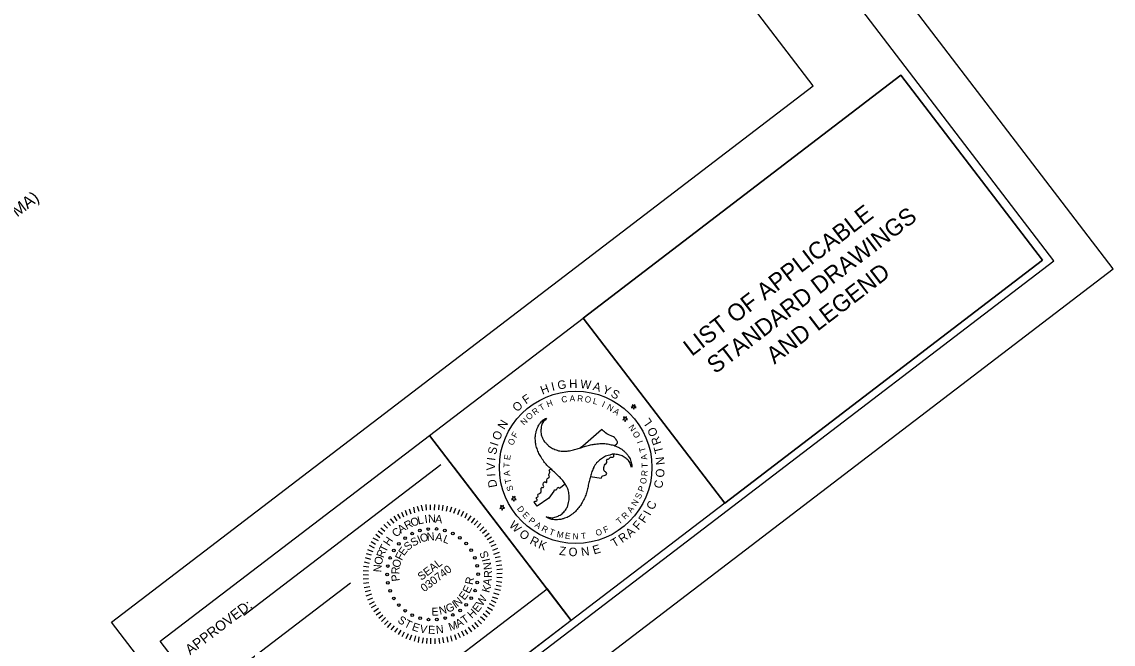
# Model space of a CAD drawing. Extents: x -642 to 2005, y -4412 to 1950.
# Drawn here: x 1361 to 2005, y 854 to 1222 of the extents above; entities that cross this region are included whole.
import ezdxf

# ---------------------------------------------------------------- set-up
doc = ezdxf.new("R2010")
doc.units = 0
for name, color, linetype in [('DEV BORDER CELL', 7, 'Continuous'), ('DEV DOT SWIRL SEAL CELL', 7, 'Continuous'), ('Old_Level_9', 7, 'Continuous'), ('Scratch_Level_0', 7, 'Continuous'), ('Scratch_Level_6', 7, 'Continuous'), ('Sheet Plot Border Outside CELL', 7, 'Continuous'), ('Sheet Sticker Exception Certification CELL', 7, 'Continuous'), ('Text', 7, 'Continuous')]:
    doc.layers.add(name, color=color, linetype=linetype)

msp = doc.modelspace()

# ---------------------------------------------------------------- linework, layer by layer
at = {"layer": 'DEV BORDER CELL'}
for p, q in [((1491.66, 871.26), (1607.91, 960.15)), ((1615.53, 958.66), (1684.78, 868.1)), ((1491.28, 841.93), (1554.67, 890.39))]:
    msp.add_line(p, q, dxfattribs=at)
for points in [[(1331.69, 1914.53), (140.13, 1003.39), (777.93, 169.29), (1969.49, 1080.44)], [(1879.29, 1189.93), (1691.82, 1046.58), (1775.34, 937.35), (1962.81, 1080.7)], [(1601.26, 977.33), (1691.82, 1046.58), (1775.34, 937.35), (1684.78, 868.1)], [(1442.35, 855.82), (1601.26, 977.33), (1684.78, 868.1), (1525.88, 746.59)]]:
    msp.add_lwpolyline(points, close=True, dxfattribs=at)
at = {"layer": 'DEV DOT SWIRL SEAL CELL'}
for p, q in [((1721.05, 994.41), (1720.19, 993.75)), ((1720.19, 993.75), (1721.28, 993.78)), ((1721.59, 994.82), (1720.7, 995.4)), ((1720.7, 995.4), (1721.05, 994.41)), ((1721.28, 993.78), (1721.66, 992.75)), ((1722.45, 995.48), (1721.59, 994.82)), ((1721.66, 992.75), (1721.94, 993.78)), ((1721.94, 993.78), (1723.03, 993.8)), ((1722.14, 994.44), (1722.45, 995.48)), ((1723.03, 993.8), (1722.14, 994.44)), ((1716.08, 987.28), (1715.22, 986.62)), ((1715.22, 986.62), (1716.31, 986.65)), ((1716.62, 987.7), (1715.73, 988.27)), ((1715.73, 988.27), (1716.08, 987.28)), ((1716.31, 986.65), (1716.69, 985.63)), ((1717.48, 988.36), (1716.62, 987.7)), ((1716.69, 985.63), (1716.97, 986.65)), ((1716.97, 986.65), (1718.06, 986.68)), ((1717.17, 987.31), (1717.48, 988.36)), ((1718.06, 986.68), (1717.17, 987.31)), ((1696.17, 953.14), (1702.42, 952.05)), ((1677.86, 946.22), (1681.23, 948.75)), ((1650.41, 940.2), (1649.55, 939.54)), ((1650.95, 940.61), (1650.06, 941.19)), ((1650.06, 941.19), (1650.41, 940.2)), ((1651.81, 941.27), (1650.95, 940.61)), ((1651.5, 940.22), (1651.81, 941.27)), ((1652.39, 939.59), (1651.5, 940.22)), ((1671.62, 940.37), (1664.76, 935.53)), ((1674.58, 944.42), (1671.62, 940.37)), ((1643.51, 934.94), (1642.65, 934.28)), ((1642.65, 934.28), (1643.74, 934.3)), ((1644.05, 935.35), (1643.15, 935.93)), ((1643.15, 935.93), (1643.51, 934.94)), ((1643.74, 934.3), (1644.12, 933.28)), ((1644.91, 936.01), (1644.05, 935.35)), ((1644.12, 933.28), (1644.4, 934.3)), ((1644.4, 934.3), (1645.49, 934.33)), ((1644.4, 934.3), (1645.49, 934.33)), ((1644.6, 934.96), (1644.91, 936.01)), ((1644.6, 934.96), (1644.91, 936.01)), ((1645.49, 934.33), (1644.6, 934.96)), ((1645.49, 934.33), (1644.6, 934.96)), ((1649.55, 939.54), (1650.64, 939.57)), ((1650.64, 939.57), (1651.02, 938.54)), ((1651.02, 938.54), (1651.3, 939.56)), ((1651.3, 939.56), (1652.39, 939.59)), ((1664.76, 935.53), (1663.22, 937.69))]:
    msp.add_line(p, q, dxfattribs=at)
for start, end in [(308.60748, 312.72752), (303.08246, 303.3802)]:
    msp.add_arc((1544.46, 1152.18), 233.19, start, end, dxfattribs=at)
for points in [[(1670.02, 929.33), (1672.63, 928.79), (1675.2, 929), (1677.58, 930.01), (1679.91, 931.59), (1681.79, 933.87), (1682.72, 935.8), (1682.96, 936.8), (1683.4, 938.52), (1683.54, 939.97), (1683.43, 942.86), (1682.76, 945.86), (1681.24, 948.73), (1681.1, 948.96), (1679.25, 951.33), (1677.09, 953.49), (1674.97, 955.56), (1672.7, 957.64), (1670.49, 959.74), (1668.67, 962.03), (1666.78, 964.81), (1665.42, 967.38), (1664.38, 970.3), (1663.93, 971.72), (1663.8, 973.04), (1663.57, 976.21), (1664.08, 979.3), (1664.59, 981.11), (1665.26, 982.57), (1665.38, 982.82), (1667.08, 985.28), (1669.23, 987.06), (1670.13, 987.44)], [(1670.14, 987.55), (1670.13, 987.44), (1668.37, 985.49), (1667.25, 983.11), (1666.93, 980.57), (1667.14, 977.78), (1668.18, 975), (1669.36, 973.23), (1670.13, 972.54), (1671.4, 971.28), (1672.57, 970.41), (1675.15, 969.11), (1678.07, 968.17), (1681.33, 968.06), (1681.6, 968.06), (1684.54, 968.45), (1687.54, 969.26), (1690.37, 970.07), (1693.29, 970.98), (1696.23, 971.81), (1699.13, 972.27), (1702.48, 972.53), (1705.37, 972.41), (1708.42, 971.88), (1709.89, 971.54), (1711.09, 970.98), (1713.96, 969.62), (1716.37, 967.62), (1717.7, 966.27), (1718.64, 964.96), (1718.81, 964.75), (1720.05, 962.01), (1720.5, 959.25), (1720.4, 958.33)], [(1710.35, 971.35), (1712.13, 973.09), (1711.23, 974.87), (1710.26, 976.18), (1708.3, 977.07), (1704.98, 978.9), (1702.68, 980.88)], [(1720.4, 958.33), (1719.58, 960.81), (1718.11, 962.96), (1716.04, 964.52), (1713.52, 965.74), (1710.61, 966.22), (1708.49, 966.08), (1707.49, 965.76), (1705.78, 965.33), (1704.42, 964.69), (1702.01, 963.15), (1699.72, 961.07), (1698.01, 958.31), (1697.88, 958.07), (1696.77, 955.3), (1695.95, 952.34), (1695.2, 949.47), (1694.56, 946.47), (1693.83, 943.49), (1692.76, 940.77), (1691.3, 937.73), (1689.75, 935.3), (1687.77, 932.94), (1686.74, 931.81), (1685.66, 931.06), (1683.07, 929.28), (1680.11, 928.16), (1678.3, 927.69), (1676.68, 927.56), (1676.4, 927.52), (1673.43, 927.79), (1670.83, 928.77), (1670.02, 929.33)], [(1702.42, 952.05), (1703.46, 953.48), (1704.91, 953.92), (1705.52, 954.24), (1705.71, 954.92), (1704.29, 956.5), (1704.07, 957.58), (1704.86, 960.31), (1705.79, 961.42), (1705.83, 963.09), (1706.19, 963.32), (1706.92, 963.42), (1707.9, 964.53), (1709.38, 964.49), (1709.89, 964.94), (1709.67, 966.12)], [(1663.22, 937.69), (1663, 937.84), (1663.19, 938.34), (1664.48, 938.69), (1664.65, 939.49), (1664.3, 939.9), (1664.38, 940.64), (1665.15, 941.02), (1665.18, 942.24), (1665.62, 942.83), (1666.81, 943.74), (1667.14, 946.23), (1667.65, 946.77), (1668.1, 946.51), (1668.51, 946.72), (1668.25, 948.36), (1668.29, 948.64), (1669.02, 949.91), (1669.48, 949.91), (1669.97, 949.47), (1670.19, 949.5), (1670.36, 950.02), (1670.38, 951.02), (1670.91, 952.18), (1672.05, 952.84), (1671.58, 953.83), (1672.17, 955.56), (1672.04, 956.24), (1671.73, 956.79)], [(1677.86, 946.22), (1677.2, 946.53), (1676.54, 946.27), (1676.09, 945.32), (1675.53, 944.93), (1674.58, 944.92), (1674.58, 944.42)]]:
    msp.add_spline(points, degree=3, dxfattribs=at)
at = {"layer": 'Old_Level_9'}
for p, q in [((1589.12, 934.01), (1590.24, 931.1)), ((1591.66, 935.01), (1592.29, 931.72)), ((1593.95, 935.51), (1594.81, 932.54)), ((1596.35, 936.08), (1596.98, 932.79)), ((1598.99, 936.53), (1599.18, 933.21)), ((1601.57, 936.46), (1601.6, 933.33)), ((1604.07, 936.48), (1604, 933.28)), ((1606.65, 936.4), (1606.42, 933.4)), ((1609.02, 936.17), (1608.68, 932.92)), ((1611.63, 935.65), (1610.96, 932.62)), ((1614.13, 935.05), (1613.11, 932.06)), ((1616.44, 934.29), (1615.42, 931.31)), ((1578.07, 928.09), (1580.05, 925.5)), ((1580.16, 929.68), (1581.83, 926.87)), ((1582.27, 930.83), (1583.9, 928.29)), ((1584.59, 932.12), (1585.91, 929.36)), ((1586.78, 933.17), (1587.9, 930.25)), ((1618.82, 933.44), (1617.63, 930.48)), ((1621.18, 932.41), (1619.64, 929.5)), ((1623.27, 931.33), (1622, 928.47)), ((1625.66, 929.85), (1623.68, 927.09)), ((1627.7, 928.42), (1625.75, 925.83)), ((1570.89, 921.02), (1573.48, 919.07)), ((1572.47, 922.86), (1574.79, 920.85)), ((1574.33, 924.75), (1576.35, 922.52)), ((1576.14, 926.29), (1578.26, 924.14)), ((1629.64, 926.92), (1627.53, 924.52)), ((1631.38, 925.26), (1629.37, 922.94)), ((1633.17, 923.32), (1630.82, 921.05)), ((1634.86, 921.31), (1632.38, 919.42)), ((1566.75, 914.7), (1569.39, 913.1)), ((1567.83, 916.79), (1570.84, 915.32)), ((1569.46, 918.98), (1571.97, 917.13)), ((1636.31, 919.43), (1633.82, 917.53)), ((1637.8, 917.27), (1635.27, 915.64)), ((1639.2, 915.03), (1636.43, 913.7)), ((1564.59, 909.91), (1567.75, 908.86)), ((1565.57, 912.54), (1568.58, 911.07)), ((1640.34, 912.92), (1637.33, 911.71)), ((1641.29, 910.65), (1638.27, 909.45)), ((1642.21, 908.21), (1638.95, 907.13)), ((1562.56, 902.69), (1565.59, 902.02)), ((1563.16, 905.2), (1566.34, 904.33)), ((1563.84, 907.6), (1566.85, 906.76)), ((1642.93, 905.61), (1639.84, 905.14)), ((1643.43, 903.32), (1640.41, 902.74)), ((1561.98, 897.68), (1565.16, 897.44)), ((1562.1, 895.26), (1565.2, 895.11)), ((1562.31, 900.14), (1565.39, 899.82)), ((1643.88, 900.67), (1640.63, 900.39)), ((1644.2, 898.4), (1640.86, 898.04)), ((1644.13, 895.83), (1640.98, 895.62)), ((1562.1, 892.59), (1565.27, 892.97)), ((1562.23, 890.16), (1565.4, 890.54)), ((1643.47, 888.24), (1640.52, 888.82)), ((1643.87, 890.6), (1640.64, 891.12)), ((1644.05, 893.25), (1640.95, 893.4)), ((1562.67, 887.52), (1565.97, 888.15)), ((1563.25, 885.12), (1566.39, 885.95)), ((1563.9, 882.63), (1567.08, 883.81)), ((1642.19, 883.33), (1639.18, 884.18)), ((1643.05, 885.71), (1639.76, 886.51)), ((1564.74, 880.28), (1567.76, 881.49)), ((1565.84, 877.82), (1568.7, 879.22)), ((1566.99, 875.71), (1569.7, 877.31)), ((1638.28, 874.04), (1635.39, 875.77)), ((1639.56, 876.28), (1636.64, 877.83)), ((1640.56, 878.47), (1637.72, 879.91)), ((1641.59, 880.83), (1638.43, 881.87)), ((1568.38, 873.47), (1571.04, 875.34)), ((1569.72, 871.51), (1572.36, 873.21)), ((1571.32, 869.42), (1573.65, 871.52)), ((1572.94, 867.51), (1575.29, 869.78)), ((1633.73, 868.05), (1631.34, 870.15)), ((1635.24, 869.99), (1632.82, 871.92)), ((1636.82, 871.83), (1634.41, 873.76)), ((1574.65, 865.68), (1576.83, 867.97)), ((1576.47, 863.92), (1578.5, 866.41)), ((1578.51, 862.49), (1580.44, 864.91)), ((1580.65, 861.13), (1582.5, 863.65)), ((1626.07, 861.41), (1624.2, 864.06)), ((1628.23, 862.9), (1626.33, 865.38)), ((1630.04, 864.44), (1627.87, 866.87)), ((1631.88, 866.16), (1629.76, 868.32)), ((1582.96, 859.75), (1584.38, 862.42)), ((1585.04, 858.67), (1586.39, 861.44)), ((1587.38, 857.47), (1588.75, 860.41)), ((1589.59, 856.64), (1590.79, 859.6)), ((1592.25, 855.84), (1593.02, 858.95)), ((1594.65, 855.16), (1595.17, 858.39)), ((1597.01, 854.76), (1597.6, 857.89)), ((1599.66, 854.58), (1599.8, 857.69)), ((1602.04, 854.36), (1602.03, 857.66)), ((1604.61, 854.28), (1604.51, 857.5)), ((1607.23, 854.55), (1606.85, 857.73)), ((1609.68, 854.85), (1609.13, 858.05)), ((1612.15, 855.33), (1611.57, 858.35)), ((1614.65, 855.97), (1613.82, 859.12)), ((1617.06, 856.72), (1616.04, 859.71)), ((1619.45, 857.92), (1618.13, 860.68)), ((1621.72, 858.86), (1620.32, 861.73)), ((1623.83, 860.01), (1622.31, 862.62))]:
    msp.add_line(p, q, dxfattribs=at)
for centre in [(1595.56, 921.17), (1600.43, 922.09), (1605.39, 922.1), (1610.26, 921.2), (1586.73, 916.75), (1590.94, 919.37), (1614.89, 919.42), (1619.11, 916.82), (1580.1, 909.44), (1583.08, 913.4), (1622.78, 913.49), (1625.77, 909.54), (1577.9, 905), (1627.99, 905.11), (1576.11, 895.29), (1576.55, 900.23), (1629.36, 900.34), (1629.83, 895.41), (1576.57, 890.36), (1629.38, 890.47), (1577.94, 885.59), (1628.03, 885.7), (1580.16, 881.16), (1583.15, 877.21), (1622.85, 877.3), (1625.83, 881.26), (1586.83, 873.88), (1591.04, 871.28), (1595.67, 869.5), (1600.54, 868.6), (1605.5, 868.61), (1610.37, 869.53), (1614.99, 871.33), (1619.2, 873.95)]:
    msp.add_circle(centre, 0.788, dxfattribs=at)
at = {"layer": 'Scratch_Level_0'}
msp.add_lwpolyline([(1322.34, 1844.44), (210.22, 994.04), (787.28, 239.38), (1485.42, 773.22), (1413.58, 867.17), (1827.56, 1183.74)], close=True, dxfattribs=at)
at = {"layer": 'Scratch_Level_6'}
msp.add_lwpolyline([(1691.82, 1046.58), (1879.29, 1189.93), (1962.81, 1080.7), (1775.34, 937.35)], close=True, dxfattribs=at)
at = {"layer": 'Sheet Plot Border Outside CELL'}
msp.add_lwpolyline([(663.64, 50.42), (2004.54, 1075.77), (1336.37, 1949.58), (-4.54, 924.23)], close=True, dxfattribs=at)
at = {"layer": 'Sheet Sticker Exception Certification CELL'}
for p, q in [((1511.6, 765.26), (1670.51, 886.77)), ((1670.51, 886.76), (1684.79, 868.09)), ((1684.78, 868.1), (1525.88, 746.59))]:
    msp.add_line(p, q, dxfattribs=at)
at = {"layer": 'Text'}
msp.add_circle((1687.42, 958.49), 44.97, dxfattribs=at)

# ---------------------------------------------------------------- texts
at = {"layer": 'DEV BORDER CELL'}
for s, height, rotation, p in [('TRUCK MOUNTED ATTENUATOR (TMA)', 7, 37.40424, (1231.07, 1009.02)), ('LIST OF APPLICABLE', 10, 37.40396, (1755.89, 1023.71)), ('STANDARD DRAWINGS ', 10, 37.40396, (1769.71, 1013.29)), ('AND LEGEND', 10, 37.40396, (1804.71, 1019.08)), ('APPROVED:  ', 6, 37.40396, (1459.96, 847.56))]:
    msp.add_text(s, height=height, rotation=rotation, dxfattribs=at).set_placement(p)
at = {"layer": 'DEV DOT SWIRL SEAL CELL'}
for s, height, rotation, p in [('H', 5.04, 20.85795, (1667.77, 1001.37)), ('I', 5.04, 13.208, (1673.67, 1003.53)), ('G', 5.04, 8.92066, (1677.08, 1004.39)), ('H', 5.04, 0.8672, (1683.63, 1005.3)), ('W', 5.04, 353.21724, (1689.9, 1005.32)), ('A', 5.04, 344.18021, (1697.24, 1004.26)), ('Y', 5.04, 337.15234, (1702.77, 1002.64)), ('F', 5.04, 34.66149, (1658.07, 995.58)), ('H', 3.63, 21.03619, (1671.02, 993.89)), ('C', 3.63, 10.88002, (1679.33, 996.57)), ('A', 3.63, 0.72385, (1683.88, 997.37)), ('R', 3.63, 355.64577, (1688.21, 997.47)), ('O', 3.63, 350.56768, (1692.52, 997.1)), ('L', 3.63, 345.4896, (1697.31, 996.13)), ('S', 5.04, 330.62886, (1707.7, 1000.55)), ('O', 5.04, 43.16891, (1652.88, 990.91)), ('R', 3.63, 36.27045, (1663.29, 989.06)), ('I', 3.63, 335.33343, (1702.47, 994.41)), ('N', 3.63, 330.25535, (1705.44, 993.02)), ('A', 3.63, 325.17726, (1709.17, 990.77)), ('N', 5.04, 58.99002, (1645.29, 980.41)), ('N', 3.63, 46.42661, (1657.04, 983.03)), ('O', 3.63, 41.34853, (1659.9, 986.12)), ('O', 5.04, 67.49744, (1642.49, 974.02)), ('F', 3.63, 61.66087, (1652.4, 975.56)), ('N', 3.63, 125.13693, (1723.35, 981.37)), ('O', 3.63, 120.33085, (1725.81, 977.12)), ('I', 5.04, 71.78478, (1641.44, 970.66)), ('O', 3.63, 66.73895, (1650.49, 971.14)), ('I', 3.63, 110.17468, (1727.23, 973.48)), ('S', 5.04, 77.98881, (1640.38, 965.68)), ('E', 3.63, 81.97321, (1648.69, 962.61)), ('T', 3.63, 105.0966, (1728.92, 967.98)), ('A', 3.63, 100.01851, (1729.79, 963.18)), ('V', 5.04, 88.98456, (1639.84, 956.69)), ('I', 5.04, 82.27614, (1639.96, 962.19)), ('T', 3.63, 87.05129, (1648.43, 958.24)), ('T', 3.63, 89.86234, (1729.96, 958.1)), ('I', 5.04, 93.2719, (1640.1, 953.18)), ('A', 3.63, 97.20746, (1648.82, 953.52)), ('R', 3.63, 84.78426, (1729.65, 953.15)), ('D', 5.04, 100.86301, (1641.19, 947.04)), ('T', 3.63, 102.28555, (1649.58, 949.33)), ('S', 3.63, 107.36363, (1650.83, 945.07)), ('P', 3.63, 69.55, (1727.3, 943.69)), ('O', 3.63, 79.70617, (1728.83, 948.41)), ('S', 3.63, 64.47192, (1725.43, 939.36)), ('D', 3.63, 307.67597, (1652.58, 934)), ('A', 3.63, 54.31575, (1720.27, 931.3)), ('N', 3.63, 59.39383, (1723.06, 935.18)), ('E', 3.63, 312.75406, (1655.62, 930.21)), ('P', 3.63, 322.91023, (1659.26, 926.44)), ('T', 3.63, 39.0815, (1713.14, 924.58)), ('R', 3.63, 44.15958, (1716.56, 927.49)), ('A', 3.63, 327.98831, (1662.93, 923.63)), ('R', 3.63, 333.0664, (1666.89, 921.2)), ('T', 3.63, 338.14448, (1671.38, 919.09)), ('M', 3.63, 348.30065, (1675.94, 917.42)), ('O', 3.63, 18.76916, (1699.85, 917.79)), ('F', 3.63, 23.84724, (1704.66, 919.6)), ('E', 3.63, 353.37873, (1680.91, 916.42)), ('N', 3.63, 358.45682, (1685.55, 915.98)), ('T', 3.63, 8.61299, (1690.89, 915.99))]:
    msp.add_text(s, height=height, rotation=rotation, dxfattribs=at).set_placement(p)
at = {"layer": 'Old_Level_9'}
for s, height, rotation, p in [('R', 4.72, 27.42552, (1587.73, 921.63)), ('O', 4.72, 20.49076, (1590.99, 923.33)), ('L', 4.72, 13.14987, (1594.65, 924.72)), ('I', 4.72, 8.20992, (1598.6, 925.53)), ('N', 4.72, 2.3078, (1600.42, 925.82)), ('A', 4.72, 354.40904, (1604.34, 925.83)), ('C', 4.72, 42.34388, (1581.58, 916.92)), ('A', 4.72, 35.37883, (1584.3, 919.32)), ('H', 4.72, 55.14731, (1577.4, 911.68)), ('S', 4.7, 41.87199, (1588.55, 909.03)), ('S', 4.7, 30.44542, (1591.65, 911.56)), ('I', 4.7, 22.88603, (1595.13, 913.59)), ('O', 4.7, 15.27885, (1596.28, 914.15)), ('N', 4.7, 4.79698, (1599.79, 915.11)), ('A', 4.7, 351.34774, (1604.37, 915.31)), ('L', 4.7, 338.93627, (1608.8, 914.45)), ('R', 4.72, 69.57941, (1574.07, 904.72)), ('T', 4.72, 62.83975, (1575.39, 907.93)), ('F', 4.7, 63.80392, (1584.83, 903.2)), ('E', 4.7, 53.9929, (1586.18, 905.96)), ('S', 4.72, 109.66185, (1636.41, 905.67)), ('O', 4.72, 77.34818, (1572.98, 900.59)), ('O', 4.7, 75.65578, (1583.54, 898.91)), ('SEAL', 4.699, 37.40396, (1596.4, 891.48)), ('I', 4.72, 103.45036, (1636.99, 903.46)), ('N', 4.72, 96.77653, (1637.96, 898.23)), ('N', 4.72, 85.47062, (1572.69, 896.43)), ('R', 4.7, 87.15176, (1583.33, 895.28)), ('030740', 4.699, 37.40396, (1598.13, 884.69)), ('R', 4.72, 88.55428, (1637.98, 893.14)), ('P', 4.7, 97.52761, (1583.71, 891.49)), ('E', 4.7, 64.56078, (1624.66, 883.62)), ('R', 4.7, 77.75323, (1626.61, 888.89)), ('K', 4.72, 73.54497, (1636.38, 884.14)), ('A', 4.72, 80.92565, (1637.27, 888.39)), ('E', 4.7, 53.20965, (1621.83, 879.72)), ('W', 4.72, 59.40972, (1632.37, 876.11)), ('E', 4.7, 2.27315, (1602.46, 870.89)), ('N', 4.7, 13.46232, (1607.35, 871.48)), ('G', 4.7, 24.88521, (1612.04, 872.55)), ('I', 4.7, 33.02855, (1616.54, 874.89)), ('N', 4.7, 40.53176, (1617.74, 875.8)), ('E', 4.72, 51.56872, (1629.67, 872.53)), ('S', 4.72, 325.61597, (1581.95, 867.35)), ('T', 4.72, 34.79055, (1621.79, 865.77)), ('H', 4.72, 43.41518, (1626.2, 868.96)), ('T', 4.72, 333.02835, (1585.8, 864.76)), ('E', 4.72, 341.22646, (1590.45, 862.53)), ('V', 4.72, 349.33376, (1595.11, 861.08)), ('E', 4.72, 357.63521, (1600.24, 860.33)), ('N', 4.72, 5.73296, (1605.19, 860.29)), ('M', 4.72, 19.741, (1613.34, 861.8)), ('A', 4.72, 27.58613, (1617.98, 863.73))]:
    msp.add_text(s, height=height, rotation=rotation, dxfattribs=at).set_placement(p)
at = {"layer": 'Text'}
for s, height, rotation, p in [('T', 3.63, 31.19236, (1667.1, 991.69)), ('L', 5.04, 124.83296, (1732.8, 985.08)), ('O', 5.04, 116.39361, (1736.21, 978.13)), ('R', 5.04, 110.15583, (1738.05, 972.71)), ('T', 5.04, 104.28498, (1739.24, 967.46)), ('N', 5.04, 96.29595, (1739.98, 960.17)), ('O', 5.04, 87.8566, (1739.66, 952.43)), ('C', 5.04, 80.48468, (1738.45, 945.78)), ('C', 5.04, 65.40726, (1733.39, 932.94)), ('W', 5.04, 315.55395, (1647.77, 923.93)), ('F', 5.04, 49.17903, (1724.41, 921.11)), ('F', 5.04, 55.16663, (1728.11, 925.18)), ('I', 5.04, 61.15423, (1731.36, 929.6)), ('O', 5.04, 324.51867, (1653.64, 918.18)), ('A', 5.04, 42.20739, (1719.6, 916.9)), ('R', 5.04, 332.95802, (1659.92, 913.66)), ('K', 5.04, 339.1958, (1664.96, 910.94)), ('T', 5.04, 30.09876, (1710.16, 911.07)), ('R', 5.04, 35.96961, (1714.89, 913.65)), ('Z', 5.04, 353.57272, (1677.47, 906.85)), ('O', 5.04, 359.92725, (1683.25, 906.07)), ('N', 5.04, 8.3666, (1690.99, 906.02)), ('E', 5.04, 16.35563, (1698.24, 907.03))]:
    msp.add_text(s, height=height, rotation=rotation, dxfattribs=at).set_placement(p)

doc.saveas('drawing.dxf')
